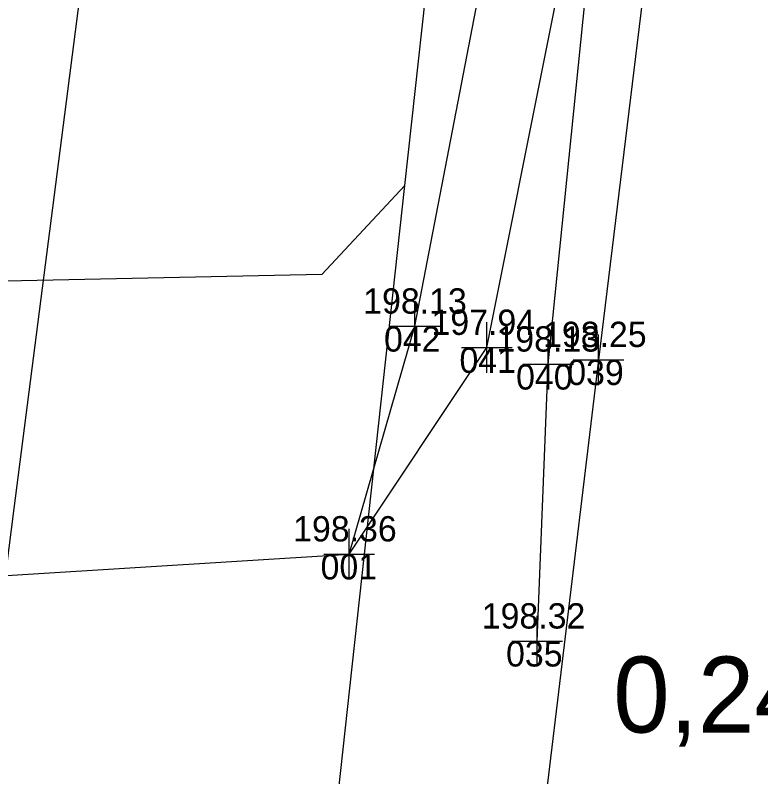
# Model space of a CAD drawing. Extents: x -706655 to -706193, y -1036183 to -1034979.
# Drawn here: x -706623.39 to -706608.67, y -1035107.9 to -1035092.86 of the extents above; entities that cross this region are included whole.
import ezdxf

# ---------------------------------------------------------------- set-up
doc = ezdxf.new("R2010")
doc.units = 0
for name, color, linetype in [('CETIN', 7, 'Continuous'), ('Hranice parcel', 7, 'Continuous'), ('křížky', 7, 'Continuous'), ('Nová vrstva (0)', 7, 'Continuous'), ('Stávající terén', 7, 'Continuous'), ('výšky', 7, 'Continuous'), ('čísla bodu', 7, 'Continuous')]:
    doc.layers.add(name, color=color, linetype=linetype)

msp = doc.modelspace()

# ---------------------------------------------------------------- linework, layer by layer
at = {"layer": 'CETIN'}
msp.add_lwpolyline([(-706632.29, -1035178.176), (-706624.38, -1035112.55), (-706623.72, -1035104.98), (-706623.414, -1035102.598), (-706615.872, -1035043.919)], dxfattribs=at)
at = {"layer": 'Hranice parcel'}
for p, q in [((-706615.7, -1035096.22), (-706606.42, -1035011.44)), ((-706615.7, -1035096.22), (-706610.89, -1035052.274)), ((-706617.66, -1035114.1), (-706615.7, -1035096.22))]:
    msp.add_line(p, q, dxfattribs=at)
msp.add_lwpolyline([(-706615.7, -1035096.22), (-706617.34, -1035097.98), (-706634.51, -1035098.34), (-706644.76, -1035099.32), (-706645.624, -1035099.305)], dxfattribs=at)
at = {"layer": 'křížky'}
for p, q in [((-706615.5, -1035099.5), (-706615.5, -1035098.5)), ((-706616, -1035099), (-706615, -1035099)), ((-706615.5, -1035099), (-706615.5, -1035099)), ((-706614.08, -1035099.92), (-706614.08, -1035098.92)), ((-706611.88, -1035100.16), (-706611.88, -1035099.16)), ((-706612.87, -1035100.25), (-706612.87, -1035099.25)), ((-706614.58, -1035099.42), (-706613.58, -1035099.42)), ((-706614.08, -1035099.42), (-706614.08, -1035099.42)), ((-706612.38, -1035099.66), (-706611.38, -1035099.66)), ((-706611.88, -1035099.66), (-706611.88, -1035099.66)), ((-706613.37, -1035099.75), (-706612.37, -1035099.75)), ((-706612.87, -1035099.75), (-706612.87, -1035099.75)), ((-706616.8, -1035104), (-706616.8, -1035103)), ((-706617.3, -1035103.5), (-706616.3, -1035103.5)), ((-706616.8, -1035103.5), (-706616.8, -1035103.5)), ((-706613.09, -1035105.72), (-706613.09, -1035104.72)), ((-706613.59, -1035105.22), (-706612.59, -1035105.22)), ((-706613.09, -1035105.22), (-706613.09, -1035105.22))]:
    msp.add_line(p, q, dxfattribs=at)
at = {"layer": 'Stávající terén'}
for points in [[(-706616.8, -1035103.5), (-706615.5, -1035099), (-706613.16, -1035086.84), (-706611.9, -1035074.82)], [(-706629.59, -1035104.3), (-706616.8, -1035103.5), (-706614.08, -1035099.42), (-706611.61, -1035087.02), (-706610.92, -1035075.19)], [(-706608.917, -1035075.29), (-706610.31, -1035086.81), (-706611.88, -1035099.66), (-706615.39, -1035128.84), (-706617.25, -1035146.23)], [(-706613.09, -1035105.22), (-706612.87, -1035099.75), (-706611.58, -1035087.02), (-706609.77, -1035075.25)]]:
    msp.add_lwpolyline(points, dxfattribs=at)
at = {"layer": 'čísla bodu'}
for p, q in [((-706615.5, -1035099.5), (-706615.5, -1035098.5)), ((-706616, -1035099), (-706615, -1035099)), ((-706615.5, -1035099), (-706615.5, -1035099)), ((-706614.08, -1035099.92), (-706614.08, -1035098.92)), ((-706611.88, -1035100.16), (-706611.88, -1035099.16)), ((-706612.87, -1035100.25), (-706612.87, -1035099.25)), ((-706614.58, -1035099.42), (-706613.58, -1035099.42)), ((-706614.08, -1035099.42), (-706614.08, -1035099.42)), ((-706612.38, -1035099.66), (-706611.38, -1035099.66)), ((-706611.88, -1035099.66), (-706611.88, -1035099.66)), ((-706613.37, -1035099.75), (-706612.37, -1035099.75)), ((-706612.87, -1035099.75), (-706612.87, -1035099.75)), ((-706616.8, -1035104), (-706616.8, -1035103)), ((-706617.3, -1035103.5), (-706616.3, -1035103.5)), ((-706616.8, -1035103.5), (-706616.8, -1035103.5)), ((-706613.09, -1035105.72), (-706613.09, -1035104.72)), ((-706613.59, -1035105.22), (-706612.59, -1035105.22)), ((-706613.09, -1035105.22), (-706613.09, -1035105.22))]:
    msp.add_line(p, q, dxfattribs=at)

# ---------------------------------------------------------------- texts
at = {"layer": 'Nová vrstva (0)'}
msp.add_text('0,242', height=1.5, dxfattribs=at).set_placement((-706611.587, -1035107.024))
at = {"layer": 'výšky'}
for s, p in [('198.13', (-706616.522, -1035098.75)), ('197.94', (-706615.174, -1035099.17)), ('198.25', (-706612.972, -1035099.41)), ('198.13', (-706613.892, -1035099.5)), ('198.36', (-706617.906, -1035103.25)), ('198.32', (-706614.182, -1035104.97))]:
    msp.add_text(s, height=0.5, dxfattribs=at).set_placement(p)
at = {"layer": 'čísla bodu'}
for s, p in [('042', (-706616.112, -1035099.5)), ('041', (-706614.622, -1035099.92)), ('039', (-706612.494, -1035100.16)), ('040', (-706613.504, -1035100.25)), ('001', (-706617.364, -1035104)), ('035', (-706613.702, -1035105.72))]:
    msp.add_text(s, height=0.5, dxfattribs=at).set_placement(p)

doc.saveas('drawing.dxf')
